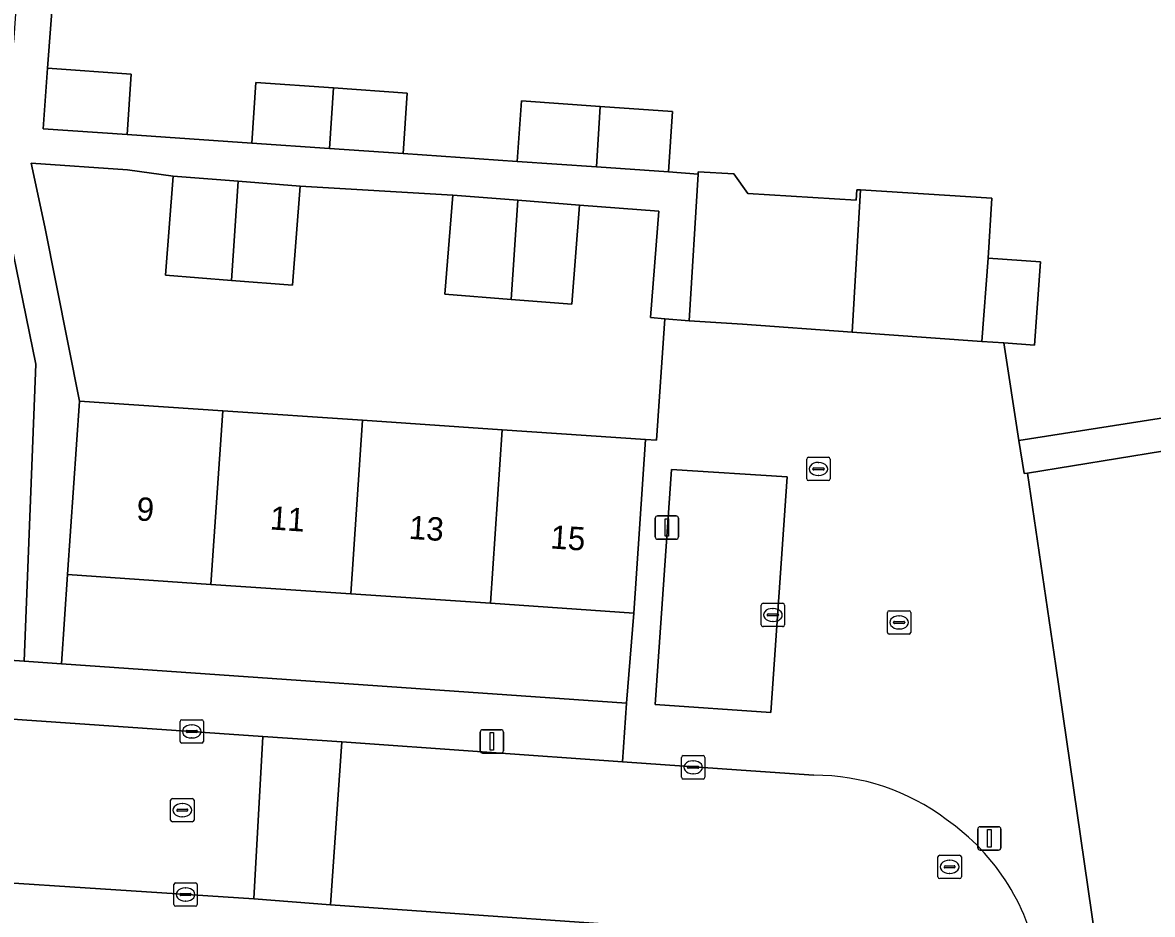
# Model space of a CAD drawing. Extents: x 159053 to 160042, y 380449 to 381423.
# Drawn here: x 159398.39 to 159446.78, y 381120.32 to 381158.52 of the extents above; entities that cross this region are included whole.
import ezdxf

# ---------------------------------------------------------------- set-up
doc = ezdxf.new("R2010")
doc.units = 0
for name, color, linetype in [('IMGEO_Erf', 7, 'Continuous'), ('IMGEO_Kolk', 7, 'Continuous'), ('IMGEO_Lichtmast', 7, 'Continuous'), ('IMGEO_Pand', 7, 'Continuous'), ('IMGEO_Pand_nummerreeks', 7, 'Continuous'), ('IMGEO_Parkeervlak_open', 7, 'Continuous'), ('IMGEO_Rijbaan_lokaal_open', 7, 'Continuous'), ('IMGEO_Rioolput', 7, 'Continuous'), ('IMGEO_Voetpad_open', 7, 'Continuous')]:
    doc.layers.add(name, color=color, linetype=linetype)

msp = doc.modelspace()

# ---------------------------------------------------------------- linework, layer by layer
at = {"layer": 'IMGEO_Erf'}
for points in [[(159395.856, 381164.312), (159396.06, 381167.421), (159398.657, 381167.233), (159399.325, 381177.147), (159374.158, 381178.842), (159370.465, 381164.045), (159365.639, 381161.495), (159363.677, 381133.592), (159398.457, 381131.162), (159398.959, 381143.89), (159397.15, 381152.623), (159396.964, 381150.031), (159393.385, 381150.287), (159393.57, 381152.879), (159388.745, 381153.224), (159388.848, 381154.667), (159395.186, 381154.243), (159395.426, 381157.83), (159398.017, 381157.657), (159398.223, 381160.746), (159395.633, 381160.919)], [(159416.813, 381151.128), (159410.274, 381151.514), (159409.942, 381147.265), (159407.337, 381147.469), (159404.507, 381147.691), (159404.84, 381151.94), (159402.883, 381152.213), (159398.76, 381152.499), (159399.339, 381149.767), (159400.819, 381142.307), (159406.959, 381141.891), (159412.946, 381141.485), (159418.932, 381141.079), (159425.073, 381140.663), (159425.535, 381140.626), (159425.903, 381145.825), (159425.276, 381145.879), (159425.634, 381150.436), (159422.247, 381150.702), (159421.915, 381146.453), (159419.31, 381146.657), (159416.48, 381146.879)], [(159449.883, 381122.105), (159449.008, 381128.041), (159448.132, 381133.977), (159447.219, 381140.164), (159441.426, 381139.219), (159442.648, 381130.967), (159447.531, 381097.239), (159453.424, 381098.108), (159452.511, 381104.298), (159451.635, 381110.234), (159450.759, 381116.17)], [(159424.569, 381133.226), (159418.428, 381133.642), (159412.442, 381134.048), (159406.455, 381134.454), (159400.315, 381134.87), (159400.049, 381131.051), (159424.259, 381129.362)]]:
    msp.add_lwpolyline(points, close=True, dxfattribs=at)
msp.add_lwpolyline([(159399.854, 381161.814), (159399.452, 381156.561), (159403.044, 381156.313), (159402.865, 381153.719), (159408.202, 381153.35), (159408.381, 381155.944), (159411.699, 381155.715), (159414.866, 381155.497), (159414.687, 381152.903), (159419.575, 381152.565), (159419.754, 381155.159), (159423.12, 381154.927), (159426.229, 381154.712), (159426.05, 381152.118), (159427.322, 381152.03), (159427.328, 381152.13), (159428.857, 381152.036), (159429.455, 381151.2), (159434.087, 381150.917), (159434.114, 381151.356), (159434.282, 381151.346), (159439.903, 381151.002), (159439.745, 381148.429), (159441.987, 381148.263), (159441.733, 381144.705), (159440.41, 381144.797), (159441.061, 381140.618), (159447.8, 381141.667)], dxfattribs=at)
at = {"layer": 'IMGEO_Kolk'}
for p, q in [((159431.977, 381138.97), (159431.977, 381139.822)), ((159432.052, 381139.896), (159432.904, 381139.896)), ((159432.978, 381139.822), (159432.978, 381138.97)), ((159432.236, 381139.39), (159432.236, 381139.402)), ((159432.674, 381139.353), (159432.276, 381139.353)), ((159432.279, 381139.439), (159432.677, 381139.439)), ((159432.465, 381139.676), (159432.49, 381139.676)), ((159432.72, 381139.402), (159432.72, 381139.39)), ((159432.904, 381138.896), (159432.052, 381138.896)), ((159432.488, 381139.116), (159432.463, 381139.116)), ((159430.027, 381132.716), (159430.027, 381133.568)), ((159430.102, 381133.642), (159430.954, 381133.642)), ((159431.028, 381133.568), (159431.028, 381132.716)), ((159430.286, 381133.136), (159430.286, 381133.148)), ((159430.724, 381133.099), (159430.326, 381133.099)), ((159430.329, 381133.185), (159430.727, 381133.185)), ((159430.515, 381133.422), (159430.54, 381133.422)), ((159430.77, 381133.148), (159430.77, 381133.136)), ((159435.429, 381132.399), (159435.429, 381133.251)), ((159435.504, 381133.325), (159436.356, 381133.325)), ((159435.917, 381133.105), (159435.942, 381133.105)), ((159436.43, 381133.251), (159436.43, 381132.399)), ((159430.954, 381132.642), (159430.102, 381132.642)), ((159430.538, 381132.862), (159430.513, 381132.862)), ((159435.688, 381132.819), (159435.688, 381132.831)), ((159436.126, 381132.782), (159435.728, 381132.782)), ((159435.731, 381132.868), (159436.129, 381132.868)), ((159435.94, 381132.545), (159435.915, 381132.545)), ((159436.172, 381132.831), (159436.172, 381132.819)), ((159436.356, 381132.325), (159435.504, 381132.325)), ((159405.208, 381128.654), (159406.06, 381128.654)), ((159405.133, 381127.728), (159405.133, 381128.58)), ((159405.392, 381128.148), (159405.392, 381128.16)), ((159405.435, 381128.197), (159405.833, 381128.197)), ((159405.621, 381128.434), (159405.646, 381128.434)), ((159405.876, 381128.16), (159405.876, 381128.148)), ((159406.134, 381128.58), (159406.134, 381127.728)), ((159406.06, 381127.654), (159405.208, 381127.654)), ((159405.83, 381128.111), (159405.432, 381128.111)), ((159405.644, 381127.874), (159405.619, 381127.874)), ((159426.611, 381126.191), (159426.611, 381127.043)), ((159426.686, 381127.117), (159427.538, 381127.117)), ((159427.099, 381126.897), (159427.124, 381126.897)), ((159427.612, 381127.043), (159427.612, 381126.191)), ((159426.87, 381126.611), (159426.87, 381126.623)), ((159427.308, 381126.574), (159426.91, 381126.574)), ((159426.913, 381126.66), (159427.311, 381126.66)), ((159427.122, 381126.337), (159427.097, 381126.337)), ((159427.354, 381126.623), (159427.354, 381126.611)), ((159427.538, 381126.117), (159426.686, 381126.117)), ((159404.869, 381120.743), (159404.869, 381121.595)), ((159404.944, 381121.669), (159405.796, 381121.669)), ((159405.357, 381121.449), (159405.382, 381121.449)), ((159405.87, 381121.595), (159405.87, 381120.743)), ((159405.128, 381121.163), (159405.128, 381121.175)), ((159405.566, 381121.126), (159405.168, 381121.126)), ((159405.171, 381121.212), (159405.569, 381121.212)), ((159405.38, 381120.889), (159405.355, 381120.889)), ((159405.612, 381121.175), (159405.612, 381121.163)), ((159405.796, 381120.669), (159404.944, 381120.669))]:
    msp.add_line(p, q, dxfattribs=at)
for points in [[(159431.977, 381138.97), (159431.977, 381139.822)], [(159432.052, 381139.896), (159432.904, 381139.896)], [(159432.978, 381139.822), (159432.978, 381138.97)], [(159432.904, 381138.896), (159432.052, 381138.896)], [(159430.027, 381132.716), (159430.027, 381133.568)], [(159430.102, 381133.642), (159430.954, 381133.642)], [(159431.028, 381133.568), (159431.028, 381132.716)], [(159435.429, 381132.399), (159435.429, 381133.251)], [(159435.504, 381133.325), (159436.356, 381133.325)], [(159436.43, 381133.251), (159436.43, 381132.399)], [(159430.954, 381132.642), (159430.102, 381132.642)], [(159436.356, 381132.325), (159435.504, 381132.325)], [(159405.208, 381128.654), (159406.06, 381128.654)], [(159405.133, 381127.728), (159405.133, 381128.58)], [(159406.134, 381128.58), (159406.134, 381127.728)], [(159406.06, 381127.654), (159405.208, 381127.654)], [(159426.611, 381126.191), (159426.611, 381127.043)], [(159426.686, 381127.117), (159427.538, 381127.117)], [(159427.612, 381127.043), (159427.612, 381126.191)], [(159427.538, 381126.117), (159426.686, 381126.117)], [(159404.869, 381120.743), (159404.869, 381121.595)], [(159404.944, 381121.669), (159405.796, 381121.669)], [(159405.87, 381121.595), (159405.87, 381120.743)], [(159405.796, 381120.669), (159404.944, 381120.669)]]:
    msp.add_lwpolyline(points, dxfattribs=at)
for centre, radius, start, end in [((159432.054, 381139.82), 0.0765, 91.552, 178.448), ((159432.054, 381139.82), 0.0765, 91.552, 178.448), ((159432.902, 381139.82), 0.0765, 1.552, 88.448), ((159432.902, 381139.82), 0.0765, 1.552, 88.448), ((159432.276, 381139.399), 0.0403, 85.8775, 175.7526), ((159432.273, 381139.389), 0.0366, 178.938, 274.7102), ((159432.677, 381139.396), 0.043, 264.8664, 352.4533), ((159432.681, 381139.401), 0.0386, 1.7309, 96.639), ((159432.054, 381138.972), 0.0765, 181.552, 268.448), ((159432.054, 381138.972), 0.0765, 181.552, 268.448), ((159432.902, 381138.972), 0.0765, 271.552, 358.448), ((159432.902, 381138.972), 0.0765, 271.552, 358.448), ((159430.104, 381133.566), 0.0765, 91.552, 178.448), ((159430.104, 381133.566), 0.0765, 91.552, 178.448), ((159430.952, 381133.566), 0.0765, 1.552, 88.448), ((159430.952, 381133.566), 0.0765, 1.552, 88.448), ((159430.326, 381133.145), 0.0403, 85.8775, 175.7526), ((159430.323, 381133.135), 0.0366, 178.938, 274.7102), ((159430.727, 381133.142), 0.043, 264.8664, 352.4533), ((159430.731, 381133.147), 0.0386, 1.7309, 96.639), ((159435.506, 381133.249), 0.0765, 91.552, 178.448), ((159435.506, 381133.249), 0.0765, 91.552, 178.448), ((159436.354, 381133.249), 0.0765, 1.552, 88.448), ((159436.354, 381133.249), 0.0765, 1.552, 88.448), ((159430.104, 381132.718), 0.0765, 181.552, 268.448), ((159430.104, 381132.718), 0.0765, 181.552, 268.448), ((159430.952, 381132.718), 0.0765, 271.552, 358.448), ((159430.952, 381132.718), 0.0765, 271.552, 358.448), ((159435.728, 381132.828), 0.0403, 85.8775, 175.7526), ((159435.725, 381132.818), 0.0366, 178.938, 274.7102), ((159436.129, 381132.825), 0.043, 264.8664, 352.4533), ((159436.133, 381132.83), 0.0386, 1.7309, 96.639), ((159435.506, 381132.401), 0.0765, 181.552, 268.448), ((159435.506, 381132.401), 0.0765, 181.552, 268.448), ((159436.354, 381132.401), 0.0765, 271.552, 358.448), ((159436.354, 381132.401), 0.0765, 271.552, 358.448), ((159405.21, 381128.578), 0.0765, 91.552, 178.448), ((159405.21, 381128.578), 0.0765, 91.552, 178.448), ((159406.058, 381128.578), 0.0765, 1.552, 88.448), ((159406.058, 381128.578), 0.0765, 1.552, 88.448), ((159405.432, 381128.157), 0.0403, 85.8775, 175.7526), ((159405.429, 381128.147), 0.0366, 178.938, 274.7102), ((159405.833, 381128.154), 0.043, 264.8664, 352.4533), ((159405.837, 381128.159), 0.0386, 1.7309, 96.639), ((159405.21, 381127.73), 0.0765, 181.552, 268.448), ((159405.21, 381127.73), 0.0765, 181.552, 268.448), ((159406.058, 381127.73), 0.0765, 271.552, 358.448), ((159406.058, 381127.73), 0.0765, 271.552, 358.448), ((159426.688, 381127.041), 0.0765, 91.552, 178.448), ((159426.688, 381127.041), 0.0765, 91.552, 178.448), ((159427.536, 381127.041), 0.0765, 1.552, 88.448), ((159427.536, 381127.041), 0.0765, 1.552, 88.448), ((159426.91, 381126.62), 0.0403, 85.8775, 175.7526), ((159426.907, 381126.61), 0.0366, 178.938, 274.7102), ((159427.311, 381126.617), 0.043, 264.8664, 352.4533), ((159427.315, 381126.622), 0.0386, 1.7309, 96.639), ((159426.688, 381126.193), 0.0765, 181.552, 268.448), ((159426.688, 381126.193), 0.0765, 181.552, 268.448), ((159427.536, 381126.193), 0.0765, 271.552, 358.448), ((159427.536, 381126.193), 0.0765, 271.552, 358.448), ((159404.946, 381121.593), 0.0765, 91.552, 178.448), ((159404.946, 381121.593), 0.0765, 91.552, 178.448), ((159405.794, 381121.593), 0.0765, 1.552, 88.448), ((159405.794, 381121.593), 0.0765, 1.552, 88.448), ((159405.168, 381121.172), 0.0403, 85.8775, 175.7526), ((159405.165, 381121.162), 0.0366, 178.938, 274.7102), ((159405.569, 381121.169), 0.043, 264.8664, 352.4533), ((159405.573, 381121.174), 0.0386, 1.7309, 96.639), ((159404.946, 381120.745), 0.0765, 181.552, 268.448), ((159404.946, 381120.745), 0.0765, 181.552, 268.448), ((159405.794, 381120.745), 0.0765, 271.552, 358.448), ((159405.794, 381120.745), 0.0765, 271.552, 358.448)]:
    msp.add_arc(centre, radius, start, end, dxfattribs=at)
for centre, major_axis, ratio, start_param, end_param in [((159432.464, 381139.396), (-0.387, 0.002), 0.722429, 4.712389, 7.853982), ((159432.489, 381139.396), (-0.39, 0.002), 0.717154, 1.570796, 4.712389), ((159430.514, 381133.142), (-0.387, 0.002), 0.722429, 4.712389, 7.853982), ((159430.539, 381133.142), (-0.39, 0.002), 0.717154, 1.570796, 4.712389), ((159435.916, 381132.825), (-0.387, 0.002), 0.722429, 4.712389, 7.853982), ((159435.941, 381132.825), (-0.39, 0.002), 0.717154, 1.570796, 4.712389), ((159405.62, 381128.154), (-0.387, 0.002), 0.722429, 4.712389, 7.853982), ((159405.645, 381128.154), (-0.39, 0.002), 0.717154, 1.570796, 4.712389), ((159427.098, 381126.617), (-0.387, 0.002), 0.722429, 4.712389, 7.853982), ((159427.123, 381126.617), (-0.39, 0.002), 0.717154, 1.570796, 4.712389), ((159405.356, 381121.169), (-0.387, 0.002), 0.722429, 4.712389, 7.853982), ((159405.381, 381121.169), (-0.39, 0.002), 0.717154, 1.570796, 4.712389)]:
    msp.add_ellipse(centre, major_axis=major_axis, ratio=ratio, start_param=start_param, end_param=end_param, dxfattribs=at)
at = {"layer": 'IMGEO_Lichtmast'}
for p, q in [((159425.587, 381137.387), (159426.377, 381137.387)), ((159426.377, 381137.387), (159425.587, 381137.387)), ((159425.487, 381136.487), (159425.487, 381137.287)), ((159425.487, 381137.287), (159425.487, 381136.487)), ((159426.477, 381137.287), (159426.477, 381136.487)), ((159426.477, 381136.487), (159426.477, 381137.287)), ((159426.377, 381136.387), (159425.587, 381136.387)), ((159425.587, 381136.387), (159426.377, 381136.387)), ((159418.091, 381128.229), (159418.881, 381128.229)), ((159418.881, 381128.229), (159418.091, 381128.229)), ((159417.991, 381127.329), (159417.991, 381128.129)), ((159417.991, 381128.129), (159417.991, 381127.329)), ((159418.981, 381128.129), (159418.981, 381127.329)), ((159418.981, 381127.329), (159418.981, 381128.129)), ((159418.881, 381127.229), (159418.091, 381127.229)), ((159418.091, 381127.229), (159418.881, 381127.229)), ((159439.3, 381123.174), (159439.3, 381123.974)), ((159439.3, 381123.974), (159439.3, 381123.174)), ((159439.4, 381124.074), (159440.19, 381124.074)), ((159440.19, 381124.074), (159439.4, 381124.074)), ((159440.29, 381123.974), (159440.29, 381123.174)), ((159440.29, 381123.174), (159440.29, 381123.974)), ((159440.19, 381123.074), (159439.4, 381123.074)), ((159439.4, 381123.074), (159440.19, 381123.074))]:
    msp.add_line(p, q, dxfattribs=at)
for points in [[(159425.907, 381137.262), (159426.057, 381137.262), (159426.057, 381136.512), (159425.907, 381136.512), (159425.907, 381137.262)], [(159418.411, 381128.104), (159418.561, 381128.104), (159418.561, 381127.354), (159418.411, 381127.354), (159418.411, 381128.104)], [(159439.72, 381123.949), (159439.87, 381123.949), (159439.87, 381123.199), (159439.72, 381123.199), (159439.72, 381123.949)]]:
    msp.add_lwpolyline(points, dxfattribs=at)
for centre, start, end in [((159425.587, 381137.287), 90, 180), ((159425.587, 381137.287), 90, 180), ((159426.377, 381137.287), 0, 90), ((159426.377, 381137.287), 360, 90), ((159425.587, 381136.487), 180, 270), ((159425.587, 381136.487), 180, 270), ((159426.377, 381136.487), 270, 0), ((159426.377, 381136.487), 270, 0), ((159418.091, 381128.129), 90, 180), ((159418.091, 381128.129), 90, 180), ((159418.881, 381128.129), 0, 90), ((159418.881, 381128.129), 360, 90), ((159418.091, 381127.329), 180, 270), ((159418.091, 381127.329), 180, 270), ((159418.881, 381127.329), 270, 0), ((159418.881, 381127.329), 270, 0), ((159439.4, 381123.974), 90, 180), ((159439.4, 381123.974), 90, 180), ((159440.19, 381123.974), 0, 90), ((159440.19, 381123.974), 360, 90), ((159439.4, 381123.174), 180, 270), ((159439.4, 381123.174), 180, 270), ((159440.19, 381123.174), 270, 0), ((159440.19, 381123.174), 270, 0)]:
    msp.add_arc(centre, 0.1, start, end, dxfattribs=at)
at = {"layer": 'IMGEO_Pand'}
for points in [[(159402.865, 381153.719), (159403.044, 381156.313), (159399.452, 381156.561), (159399.273, 381153.967)], [(159411.535, 381153.12), (159411.699, 381155.715), (159408.381, 381155.944), (159408.202, 381153.35)], [(159411.535, 381153.12), (159414.687, 381152.903), (159414.866, 381155.497), (159411.699, 381155.715)], [(159423.12, 381154.927), (159419.754, 381155.159), (159419.575, 381152.565), (159422.969, 381152.331)], [(159423.12, 381154.927), (159422.969, 381152.331), (159426.05, 381152.118), (159426.229, 381154.712)], [(159407.337, 381147.469), (159407.625, 381151.722), (159404.84, 381151.94), (159404.507, 381147.691)], [(159434.282, 381151.346), (159434.114, 381151.356), (159434.087, 381150.917), (159429.455, 381151.2), (159428.857, 381152.036), (159427.328, 381152.13), (159427.322, 381152.03), (159426.937, 381145.736), (159429.225, 381145.596), (159433.918, 381145.257)], [(159407.337, 381147.469), (159409.942, 381147.265), (159410.274, 381151.514), (159407.625, 381151.722)], [(159419.31, 381146.657), (159419.598, 381150.91), (159416.813, 381151.128), (159416.48, 381146.879)], [(159419.31, 381146.657), (159421.915, 381146.453), (159422.247, 381150.702), (159419.598, 381150.91)], [(159434.282, 381151.346), (159433.918, 381145.257), (159437.288, 381145.013), (159439.474, 381144.862), (159439.745, 381148.429), (159439.903, 381151.002)], [(159439.474, 381144.862), (159440.41, 381144.797), (159441.733, 381144.705), (159441.987, 381148.263), (159439.745, 381148.429)], [(159406.455, 381134.454), (159406.959, 381141.891), (159400.819, 381142.307), (159400.315, 381134.87)], [(159412.946, 381141.485), (159406.959, 381141.891), (159406.455, 381134.454), (159412.442, 381134.048)], [(159412.946, 381141.485), (159412.442, 381134.048), (159418.428, 381133.642), (159418.932, 381141.079)], [(159418.932, 381141.079), (159418.428, 381133.642), (159424.569, 381133.226), (159425.073, 381140.663)]]:
    msp.add_lwpolyline(points, close=True, dxfattribs=at)
at = {"layer": 'IMGEO_Parkeervlak_open'}
msp.add_lwpolyline([(159430.438, 381128.966), (159431.142, 381139.062), (159426.185, 381139.368), (159425.481, 381129.313)], close=True, dxfattribs=at)
at = {"layer": 'IMGEO_Rijbaan_lokaal_open'}
for points in [[(159408.675, 381127.944), (159347.843, 381132.155), (159347.425, 381125.142), (159367.896, 381123.741), (159390.325, 381122.15), (159408.288, 381120.979)], [(159412.055, 381127.71), (159408.675, 381127.944), (159408.288, 381120.979), (159411.579, 381120.723)]]:
    msp.add_lwpolyline(points, close=True, dxfattribs=at)
msp.add_lwpolyline([(159432.282, 381126.275), (159429.161, 381126.499), (159424.078, 381126.859), (159412.055, 381127.71), (159411.579, 381120.723), (159428.777, 381119.532), (159430.026, 381119.52)], dxfattribs=at)
for centre, radius, start, end in [((159432.306, 381116.895), 9.38, 52.9967, 90.1455), ((159432.499, 381116.558), 9.539, 8.5595, 55.1421)]:
    msp.add_arc(centre, radius, start, end, dxfattribs=at)
at = {"layer": 'IMGEO_Rioolput'}
for p, q in [((159404.805, 381125.282), (159405.657, 381125.282)), ((159404.73, 381124.356), (159404.73, 381125.208)), ((159404.989, 381124.776), (159404.989, 381124.788)), ((159405.032, 381124.825), (159405.43, 381124.825)), ((159405.218, 381125.062), (159405.243, 381125.062)), ((159405.473, 381124.788), (159405.473, 381124.776)), ((159405.731, 381125.208), (159405.731, 381124.356)), ((159405.657, 381124.282), (159404.805, 381124.282)), ((159405.427, 381124.739), (159405.029, 381124.739)), ((159405.241, 381124.502), (159405.216, 381124.502)), ((159437.671, 381122.854), (159438.523, 381122.854)), ((159437.596, 381121.928), (159437.596, 381122.78)), ((159437.855, 381122.348), (159437.855, 381122.36)), ((159437.898, 381122.397), (159438.296, 381122.397)), ((159438.084, 381122.634), (159438.109, 381122.634)), ((159438.339, 381122.36), (159438.339, 381122.348)), ((159438.597, 381122.78), (159438.597, 381121.928)), ((159438.523, 381121.854), (159437.671, 381121.854)), ((159438.293, 381122.311), (159437.895, 381122.311)), ((159438.107, 381122.074), (159438.082, 381122.074))]:
    msp.add_line(p, q, dxfattribs=at)
for points in [[(159404.805, 381125.282), (159405.657, 381125.282)], [(159404.73, 381124.356), (159404.73, 381125.208)], [(159405.731, 381125.208), (159405.731, 381124.356)], [(159405.657, 381124.282), (159404.805, 381124.282)], [(159437.671, 381122.854), (159438.523, 381122.854)], [(159437.596, 381121.928), (159437.596, 381122.78)], [(159438.597, 381122.78), (159438.597, 381121.928)], [(159438.523, 381121.854), (159437.671, 381121.854)]]:
    msp.add_lwpolyline(points, dxfattribs=at)
for centre, radius, start, end in [((159404.807, 381125.206), 0.0765, 91.552, 178.448), ((159404.807, 381125.206), 0.0765, 91.552, 178.448), ((159405.655, 381125.206), 0.0765, 1.552, 88.448), ((159405.655, 381125.206), 0.0765, 1.552, 88.448), ((159405.029, 381124.785), 0.0403, 85.8775, 175.7526), ((159405.026, 381124.775), 0.0366, 178.938, 274.7102), ((159405.43, 381124.782), 0.043, 264.8664, 352.4533), ((159405.434, 381124.787), 0.0386, 1.7309, 96.639), ((159404.807, 381124.358), 0.0765, 181.552, 268.448), ((159404.807, 381124.358), 0.0765, 181.552, 268.448), ((159405.655, 381124.358), 0.0765, 271.552, 358.448), ((159405.655, 381124.358), 0.0765, 271.552, 358.448), ((159437.673, 381122.778), 0.0765, 91.552, 178.448), ((159437.673, 381122.778), 0.0765, 91.552, 178.448), ((159438.521, 381122.778), 0.0765, 1.552, 88.448), ((159438.521, 381122.778), 0.0765, 1.552, 88.448), ((159437.895, 381122.357), 0.0403, 85.8775, 175.7526), ((159437.892, 381122.347), 0.0366, 178.938, 274.7102), ((159438.296, 381122.354), 0.043, 264.8664, 352.4533), ((159438.3, 381122.359), 0.0386, 1.7309, 96.639), ((159437.673, 381121.93), 0.0765, 181.552, 268.448), ((159437.673, 381121.93), 0.0765, 181.552, 268.448), ((159438.521, 381121.93), 0.0765, 271.552, 358.448), ((159438.521, 381121.93), 0.0765, 271.552, 358.448)]:
    msp.add_arc(centre, radius, start, end, dxfattribs=at)
for centre, major_axis, ratio, start_param, end_param in [((159405.217, 381124.782), (-0.387, 0.002), 0.722429, 4.712389, 7.853982), ((159405.242, 381124.782), (-0.39, 0.002), 0.717154, 1.570796, 4.712389), ((159438.083, 381122.354), (-0.387, 0.002), 0.722429, 4.712389, 7.853982), ((159438.108, 381122.354), (-0.39, 0.002), 0.717154, 1.570796, 4.712389)]:
    msp.add_ellipse(centre, major_axis=major_axis, ratio=ratio, start_param=start_param, end_param=end_param, dxfattribs=at)
at = {"layer": 'IMGEO_Voetpad_open'}
for points in [[(159397.15, 381152.623), (159398.959, 381143.89), (159398.457, 381131.162), (159400.049, 381131.051), (159400.315, 381134.87), (159400.819, 381142.307), (159399.339, 381149.767), (159398.76, 381152.499), (159402.883, 381152.213), (159404.84, 381151.94), (159407.625, 381151.722), (159410.274, 381151.514), (159416.813, 381151.128), (159419.598, 381150.91), (159422.247, 381150.702), (159425.634, 381150.436), (159425.276, 381145.879), (159425.903, 381145.825), (159426.937, 381145.736), (159427.322, 381152.03), (159426.05, 381152.118), (159422.969, 381152.331), (159419.575, 381152.565), (159414.687, 381152.903), (159411.535, 381153.12), (159408.202, 381153.35), (159402.865, 381153.719), (159399.273, 381153.967), (159399.452, 381156.561), (159399.854, 381161.814)], [(159448.814, 381088.274), (159448.096, 381093.308), (159447.686, 381096.187), (159447.619, 381096.645), (159447.531, 381097.239), (159442.648, 381130.967), (159441.426, 381139.219), (159441.281, 381139.203), (159441.061, 381140.618), (159440.41, 381144.797), (159439.474, 381144.862), (159437.288, 381145.013), (159433.918, 381145.257), (159429.225, 381145.596), (159426.937, 381145.736), (159425.903, 381145.825), (159425.535, 381140.626), (159425.073, 381140.663), (159424.569, 381133.226), (159424.259, 381129.362), (159424.078, 381126.859), (159429.161, 381126.499), (159432.282, 381126.275)], [(159447.8, 381141.667), (159441.061, 381140.618), (159441.281, 381139.203), (159441.426, 381139.219), (159447.219, 381140.164)], [(159316.193, 381134.269), (159320.6, 381133.986), (159325.192, 381133.689), (159330.073, 381133.355), (159335.084, 381133.041), (159344.386, 381132.385), (159347.843, 381132.155), (159408.675, 381127.944), (159412.055, 381127.71), (159424.078, 381126.859), (159424.259, 381129.362), (159400.049, 381131.051), (159398.457, 381131.162), (159363.677, 381133.592)], [(159430.026, 381119.52), (159428.777, 381119.532), (159411.579, 381120.723), (159408.288, 381120.979), (159390.325, 381122.15), (159382.229, 381121.007)]]:
    msp.add_lwpolyline(points, dxfattribs=at)
msp.add_lwpolyline([(159425.481, 381129.313), (159426.185, 381139.368), (159431.142, 381139.062), (159430.438, 381128.966)], close=True, dxfattribs=at)
for centre, radius, start, end in [((159432.306, 381116.895), 9.38, 52.9967, 90.1455), ((159432.499, 381116.558), 9.539, 8.5595, 55.1421)]:
    msp.add_arc(centre, radius, start, end, dxfattribs=at)

# ---------------------------------------------------------------- texts
at = {"layer": 'IMGEO_Pand_nummerreeks'}
for s, p in [('9', (159403.242, 381137.198)), ('11', (159408.961, 381136.81)), ('13', (159414.911, 381136.406)), ('15', (159420.974, 381135.995))]:
    msp.add_text(s, height=1, rotation=356.1223, dxfattribs=at).set_placement(p)

doc.saveas('drawing.dxf')
